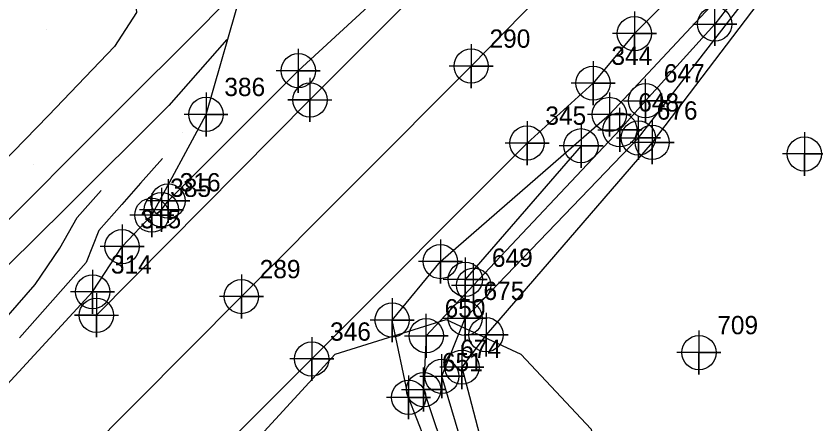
# Model space of a CAD drawing. Extents: x 1497074 to 1501343, y 481943 to 486114.
# Drawn here: x 1499153.8 to 1499263, y 485520.4 to 485576.1 of the extents above; entities that cross this region are included whole.
import ezdxf

# ---------------------------------------------------------------- set-up
doc = ezdxf.new("R2010")
doc.units = 0
for name, color, linetype in [('Exist DTM Breakline', 7, 'Continuous'), ('Exist DTM Breakline Cogo Point CELL', 7, 'Continuous'), ('Exist DTM Crownline', 7, 'Continuous'), ('Exist DTM Crownline Cogo Number', 7, 'Continuous'), ('Exist DTM Crownline Cogo Point CELL', 7, 'Continuous'), ('Exist DTM Regular Point CELL', 7, 'Continuous'), ('Exist DTM Regular Point Cogo Number', 7, 'Continuous'), ('Exist Hydro Stream or Body of Water', 7, 'Continuous'), ('Exist Hydro Stream or Body of Water Cogo Number', 7, 'Continuous'), ('Exist Hydro Stream or Body of Water Cogo Point CELL', 7, 'Continuous'), ('Exist Roads EOP', 7, 'Continuous'), ('Exist Roads EOP Cogo Number', 7, 'Continuous'), ('Exist Roads EOP Cogo Point CELL', 7, 'Continuous'), ('Exist Roads EOT', 7, 'Continuous'), ('Exist Roads EOT Cogo Point CELL', 7, 'Continuous'), ('PH Exist DTM Breakline', 7, 'Continuous'), ('PH Exist DTM Obscure Area', 7, 'Continuous'), ('PH Exist DTM Point', 7, 'Continuous')]:
    doc.layers.add(name, color=color, linetype=linetype)

msp = doc.modelspace()

# ---------------------------------------------------------------- linework, layer by layer
at = {"layer": 'Exist DTM Breakline'}
msp.add_line((1499230.94, 485558.36), (1499215.12, 485540.11), dxfattribs=at)
for points in [[(1499185.98, 485341), (1499182.42, 485376.38), (1499182.27, 485405.43), (1499187.88, 485425.83), (1499196.82, 485454.89), (1499202.61, 485465.75), (1499208.87, 485482.28), (1499210.41, 485491.89), (1499215.33, 485503.59), (1499207.38, 485524), (1499205.13, 485534.56), (1499211.72, 485542.55), (1499234.8, 485562.64), (1499257.12, 485586.54)], [(1499260.16, 485584.5), (1499240.65, 485558.83), (1499217.96, 485532.56), (1499214.66, 485528.12), (1499220.52, 485505.65), (1499216.85, 485483.92), (1499209.67, 485464.86), (1499198.25, 485439.29), (1499192.7, 485425), (1499191.35, 485405.79), (1499191.24, 485397.87), (1499188.24, 485373.03), (1499195.27, 485338.64)], [(1499173.62, 485549.63), (1499174.52, 485550.82), (1499192.31, 485568.61), (1499205.81, 485581.06)]]:
    msp.add_lwpolyline(points, dxfattribs=at)
at = {"layer": 'Exist DTM Breakline Cogo Point CELL'}
for points in [[(1499192.31, 485571.61), (1499192.31, 485565.61), (1499192.31, 485568.61), (1499195.31, 485568.61), (1499189.31, 485568.61)], [(1499234.8, 485565.64), (1499234.8, 485559.64), (1499234.8, 485562.64), (1499237.8, 485562.64), (1499231.8, 485562.64)], [(1499240.65, 485561.83), (1499240.65, 485555.83), (1499240.65, 485558.83), (1499243.65, 485558.83), (1499237.65, 485558.83)], [(1499230.94, 485561.36), (1499230.94, 485555.36), (1499230.94, 485558.36), (1499233.94, 485558.36), (1499227.94, 485558.36)], [(1499174.52, 485553.82), (1499174.52, 485547.82), (1499174.52, 485550.82), (1499177.52, 485550.82), (1499171.52, 485550.82)], [(1499211.72, 485545.55), (1499211.72, 485539.55), (1499211.72, 485542.55), (1499214.72, 485542.55), (1499208.72, 485542.55)], [(1499215.12, 485543.11), (1499215.12, 485537.11), (1499215.12, 485540.11), (1499218.12, 485540.11), (1499212.12, 485540.11)], [(1499205.13, 485537.56), (1499205.13, 485531.56), (1499205.13, 485534.56), (1499208.13, 485534.56), (1499202.13, 485534.56)], [(1499217.96, 485535.56), (1499217.96, 485529.56), (1499217.96, 485532.56), (1499220.96, 485532.56), (1499214.96, 485532.56)], [(1499214.66, 485531.12), (1499214.66, 485525.12), (1499214.66, 485528.12), (1499217.66, 485528.12), (1499211.66, 485528.12)], [(1499207.38, 485527), (1499207.38, 485521), (1499207.38, 485524), (1499210.38, 485524), (1499204.38, 485524)]]:
    msp.add_lwpolyline(points, dxfattribs=at)
for centre in [(1499192.31, 485568.61), (1499234.8, 485562.64), (1499230.94, 485558.36), (1499240.65, 485558.83), (1499174.52, 485550.82), (1499211.72, 485542.55), (1499215.12, 485540.11), (1499205.13, 485534.56), (1499217.96, 485532.56), (1499214.66, 485528.12), (1499207.38, 485524)]:
    msp.add_circle(centre, 2.34, dxfattribs=at)
at = {"layer": 'Exist DTM Crownline'}
msp.add_lwpolyline([(1498753.92, 485018.83), (1498767.97, 485036.35), (1498784.41, 485057.61), (1498813.33, 485094.71), (1498845.11, 485135.39), (1498876.05, 485175.22), (1498907.7, 485215.72), (1498939.87, 485257.15), (1498970.73, 485296.32), (1499001.6, 485335.5), (1499032.55, 485374.36), (1499053.88, 485400.5), (1499073.91, 485423.48), (1499090.49, 485441.64), (1499112.37, 485464.57), (1499148.43, 485501.47), (1499184.54, 485537.77), (1499215.93, 485569.25), (1499248.51, 485602.52), (1499285.02, 485638.96), (1499320.99, 485674.8), (1499344.91, 485698.57), (1499374.04, 485727.35), (1499398.21, 485750.96)], dxfattribs=at)
at = {"layer": 'Exist DTM Crownline Cogo Point CELL'}
for points in [[(1499215.93, 485572.25), (1499215.93, 485566.25), (1499215.93, 485569.25), (1499218.93, 485569.25), (1499212.93, 485569.25)], [(1499184.54, 485540.77), (1499184.54, 485534.77), (1499184.54, 485537.77), (1499187.54, 485537.77), (1499181.54, 485537.77)]]:
    msp.add_lwpolyline(points, dxfattribs=at)
for centre in [(1499215.93, 485569.25), (1499184.54, 485537.77)]:
    msp.add_circle(centre, 2.34, dxfattribs=at)
at = {"layer": 'Exist DTM Regular Point CELL'}
for points in [[(1499261.44, 485560.24), (1499261.44, 485554.24), (1499261.44, 485557.24), (1499264.44, 485557.24), (1499258.44, 485557.24)], [(1499247.04, 485533.12), (1499247.04, 485527.12), (1499247.04, 485530.12), (1499250.04, 485530.12), (1499244.04, 485530.12)]]:
    msp.add_lwpolyline(points, dxfattribs=at)
for centre in [(1499261.44, 485557.24), (1499247.04, 485530.12)]:
    msp.add_circle(centre, 2.34, dxfattribs=at)
at = {"layer": 'Exist Hydro Stream or Body of Water'}
for points in [[(1499257.73, 485586.04), (1499249.2, 485574.99), (1499239.74, 485564.51)], [(1499192.72, 485337.9), (1499186.72, 485373.56), (1499186.02, 485389.81), (1499189.55, 485398.75), (1499188.74, 485407.91), (1499191.43, 485426.99), (1499196.42, 485439.19), (1499206.35, 485461.87), (1499214.78, 485484.46), (1499216.03, 485490.1), (1499217.88, 485506.83), (1499211.92, 485526.88), (1499215.11, 485534.8), (1499238.77, 485559.43), (1499259.03, 485585.66)], [(1499239.74, 485564.51), (1499236.24, 485560.54), (1499216.26, 485539.33), (1499209.8, 485532.42), (1499209.43, 485525.06), (1499216.54, 485503.87), (1499211.37, 485491.89), (1499211.32, 485490.81), (1499211, 485482.57), (1499204.46, 485465.7), (1499198.37, 485454.49), (1499189.02, 485425.2), (1499187.48, 485405.82), (1499185.13, 485390.06), (1499184.69, 485374.49), (1499190.61, 485338.3)]]:
    msp.add_lwpolyline(points, dxfattribs=at)
at = {"layer": 'Exist Hydro Stream or Body of Water Cogo Point CELL'}
for points in [[(1499246.2, 485574.99), (1499252.2, 485574.99), (1499249.2, 485574.99), (1499249.2, 485571.99), (1499249.2, 485577.99)], [(1499236.74, 485564.51), (1499242.74, 485564.51), (1499239.74, 485564.51), (1499239.74, 485561.51), (1499239.74, 485567.51)], [(1499233.24, 485560.54), (1499239.24, 485560.54), (1499236.24, 485560.54), (1499236.24, 485557.54), (1499236.24, 485563.54)], [(1499235.77, 485559.43), (1499241.77, 485559.43), (1499238.77, 485559.43), (1499238.77, 485556.43), (1499238.77, 485562.43)], [(1499213.26, 485539.33), (1499219.26, 485539.33), (1499216.26, 485539.33), (1499216.26, 485536.33), (1499216.26, 485542.33)], [(1499212.11, 485534.8), (1499218.11, 485534.8), (1499215.11, 485534.8), (1499215.11, 485531.8), (1499215.11, 485537.8)], [(1499206.8, 485532.42), (1499212.8, 485532.42), (1499209.8, 485532.42), (1499209.8, 485529.42), (1499209.8, 485535.42)], [(1499208.92, 485526.88), (1499214.92, 485526.88), (1499211.92, 485526.88), (1499211.92, 485523.88), (1499211.92, 485529.88)], [(1499206.43, 485525.06), (1499212.43, 485525.06), (1499209.43, 485525.06), (1499209.43, 485522.06), (1499209.43, 485528.06)]]:
    msp.add_lwpolyline(points, dxfattribs=at)
for centre in [(1499249.2, 485574.99), (1499239.74, 485564.51), (1499236.24, 485560.54), (1499238.77, 485559.43), (1499216.26, 485539.33), (1499215.11, 485534.8), (1499209.8, 485532.42), (1499211.92, 485526.88), (1499209.43, 485525.06)]:
    msp.add_circle(centre, 2.34, dxfattribs=at)
at = {"layer": 'Exist Roads EOP'}
for points in [[(1499406.68, 485742.77), (1499382.28, 485717.88), (1499354.16, 485689.77), (1499330.28, 485665.86), (1499294.21, 485630.03), (1499257.75, 485593.24), (1499238.22, 485573.68), (1499232.58, 485566.91), (1499223.56, 485558.73), (1499194.15, 485529.24), (1499157.4, 485492.59), (1499121.26, 485455.44)], [(1499172.31, 485548.88), (1499179.71, 485562.65), (1499184.8, 485580.27), (1499188.78, 485607.06), (1499189.23, 485622.67), (1499188.38, 485633.27), (1499185.84, 485649.44), (1499182.84, 485660.02), (1499178.88, 485670.13), (1499176.46, 485674.89), (1499173.56, 485679.31), (1499157.76, 485701.6)], [(1498744.68, 485026.11), (1498757.92, 485043.98), (1498774.18, 485065.51), (1498803.2, 485102.83), (1498835.11, 485143.9), (1498866.39, 485184.06), (1498897.92, 485224.48), (1498930.45, 485265.81), (1498960.65, 485304.75), (1498991.78, 485343.69), (1499023.06, 485383.27), (1499044.83, 485409.1), (1499064.02, 485432.02), (1499081.8, 485451.06), (1499098.44, 485468.79), (1499108.29, 485478.99), (1499123.4, 485494.87), (1499138.72, 485510.78), (1499164.22, 485538.41), (1499168.24, 485544.59), (1499172.31, 485548.88)]]:
    msp.add_lwpolyline(points, dxfattribs=at)
at = {"layer": 'Exist Roads EOP Cogo Point CELL'}
for points in [[(1499238.22, 485576.68), (1499238.22, 485570.68), (1499238.22, 485573.68), (1499241.22, 485573.68), (1499235.22, 485573.68)], [(1499232.58, 485569.91), (1499232.58, 485563.91), (1499232.58, 485566.91), (1499235.58, 485566.91), (1499229.58, 485566.91)], [(1499179.71, 485565.65), (1499179.71, 485559.65), (1499179.71, 485562.65), (1499182.71, 485562.65), (1499176.71, 485562.65)], [(1499223.56, 485561.73), (1499223.56, 485555.73), (1499223.56, 485558.73), (1499226.56, 485558.73), (1499220.56, 485558.73)], [(1499173.62, 485552.63), (1499173.62, 485546.63), (1499173.62, 485549.63), (1499176.62, 485549.63), (1499170.62, 485549.63)], [(1499172.31, 485551.88), (1499172.31, 485545.88), (1499172.31, 485548.88), (1499175.31, 485548.88), (1499169.31, 485548.88)], [(1499168.24, 485547.59), (1499168.24, 485541.59), (1499168.24, 485544.59), (1499171.24, 485544.59), (1499165.24, 485544.59)], [(1499164.22, 485541.41), (1499164.22, 485535.41), (1499164.22, 485538.41), (1499167.22, 485538.41), (1499161.22, 485538.41)], [(1499194.15, 485532.24), (1499194.15, 485526.24), (1499194.15, 485529.24), (1499197.15, 485529.24), (1499191.15, 485529.24)]]:
    msp.add_lwpolyline(points, dxfattribs=at)
for centre in [(1499238.22, 485573.68), (1499232.58, 485566.91), (1499179.71, 485562.65), (1499223.56, 485558.73), (1499173.62, 485549.63), (1499172.31, 485548.88), (1499168.24, 485544.59), (1499164.22, 485538.41), (1499194.15, 485529.24)]:
    msp.add_circle(centre, 2.34, dxfattribs=at)
at = {"layer": 'Exist Roads EOT'}
msp.add_lwpolyline([(1499164.74, 485535.21), (1499193.9, 485564.62), (1499219.81, 485590.53), (1499263, 485633.71)], dxfattribs=at)
at = {"layer": 'Exist Roads EOT Cogo Point CELL'}
for points in [[(1499193.9, 485567.62), (1499193.9, 485561.62), (1499193.9, 485564.62), (1499190.9, 485564.62), (1499196.9, 485564.62)], [(1499164.74, 485538.21), (1499164.74, 485532.21), (1499164.74, 485535.21), (1499161.74, 485535.21), (1499167.74, 485535.21)]]:
    msp.add_lwpolyline(points, dxfattribs=at)
for centre in [(1499193.9, 485564.62), (1499164.74, 485535.21)]:
    msp.add_circle(centre, 2.34, dxfattribs=at)
at = {"layer": 'PH Exist DTM Breakline'}
for points in [[(1499153.17, 485673.71), (1499162.45, 485658.84), (1499165.18, 485653.77), (1499167.02, 485648.89), (1499168.88, 485643.09), (1499170.56, 485637.72), (1499171.57, 485631.53), (1499171.4, 485625.48), (1499170.63, 485618.57), (1499170.84, 485611.93), (1499171.01, 485605.52), (1499171.2, 485599.72), (1499170.74, 485593.96), (1499169.59, 485586.49), (1499169.76, 485581.42), (1499170.2, 485576.57), (1499167.23, 485571.91), (1499158.21, 485562.48), (1499132.52, 485536.14)], [(1499033.33, 485421.86), (1499038.75, 485428.05), (1499042.42, 485431.01), (1499046.18, 485433.54), (1499048.33, 485435.36), (1499050.55, 485437.83), (1499053.16, 485442.2), (1499056.29, 485447.97), (1499058.09, 485450.12), (1499066.63, 485459.29), (1499087.71, 485481.69), (1499111.87, 485506.97), (1499131.84, 485527.59), (1499149.97, 485545.53), (1499167.07, 485562.63), (1499179.36, 485574.9), (1499184.32, 485580.01)], [(1499182.56, 485572.89), (1499174.63, 485563.86), (1499160.52, 485549.79), (1499140.85, 485530.42), (1499113.26, 485502.35), (1499086.18, 485474.29), (1499062.04, 485447.92), (1499060.27, 485445.67), (1499058.22, 485441.12), (1499056.49, 485438.04), (1499054.74, 485435.42), (1499052.19, 485432.56), (1499050.32, 485430.5), (1499046.87, 485427.89), (1499042.32, 485424.66), (1499039.45, 485422.45), (1499036.52, 485418.7)], [(1499173.78, 485556.64), (1499170.74, 485553.24), (1499168.2, 485550.36), (1499165.05, 485546.8), (1499163.33, 485542.41), (1499154.23, 485532.15)], [(1499134.85, 485515.78), (1499151.43, 485533.79), (1499156.37, 485539.4), (1499159.74, 485544.39), (1499162.09, 485548.56), (1499165.38, 485552.24)]]:
    msp.add_lwpolyline(points, dxfattribs=at)
at = {"layer": 'PH Exist DTM Obscure Area'}
msp.add_lwpolyline([(1499149.23, 485468.18), (1499156.41, 485483.23), (1499168.58, 485498.07), (1499183.61, 485514.9), (1499197.34, 485529.91), (1499212.52, 485534.63), (1499222.72, 485529.9), (1499232.31, 485519.64), (1499234.08, 485508.3), (1499229.88, 485495.42), (1499220.2, 485480.12), (1499219.41, 485460.49), (1499225.77, 485441.12), (1499228.02, 485432.48), (1499228.46, 485418.31), (1499232.97, 485402.23), (1499241.35, 485391.01), (1499261.85, 485386.79), (1499278, 485376.9), (1499289.37, 485366.83), (1499301.98, 485354.41), (1499307.09, 485337.87), (1499311.37, 485319.99), (1499317.64, 485301.29)], dxfattribs=at)
at = {"layer": 'PH Exist DTM Point'}
for p, q in [((1499157.95, 485574.21), (1499157.95, 485574.21)), ((1499176.47, 485560.14), (1499176.47, 485560.14)), ((1499156.2, 485555.77), (1499156.2, 485555.77))]:
    msp.add_line(p, q, dxfattribs=at)

# ---------------------------------------------------------------- texts
at = {"layer": 'Exist DTM Crownline Cogo Number'}
for s, p in [('290', (1499218.43, 485571.75)), ('289', (1499187.04, 485540.27))]:
    msp.add_text(s, height=2.5, dxfattribs=at).set_placement(p)
at = {"layer": 'Exist DTM Regular Point Cogo Number'}
msp.add_text('709', height=2.5, dxfattribs=at).set_placement((1499249.54, 485532.62))
at = {"layer": 'Exist Hydro Stream or Body of Water Cogo Number'}
for s, p in [('647', (1499242.24, 485567.01)), ('648', (1499238.74, 485563.04)), ('676', (1499241.27, 485561.93)), ('649', (1499218.76, 485541.83)), ('675', (1499217.61, 485537.3)), ('650', (1499212.3, 485534.92)), ('674', (1499214.42, 485529.38)), ('651', (1499211.93, 485527.56))]:
    msp.add_text(s, height=2.5, dxfattribs=at).set_placement(p)
at = {"layer": 'Exist Roads EOP Cogo Number'}
for s, p in [('344', (1499235.08, 485569.41)), ('386', (1499182.21, 485565.15)), ('345', (1499226.06, 485561.23)), ('316', (1499176.12, 485552.13)), ('385', (1499174.81, 485551.38)), ('315', (1499170.74, 485547.09)), ('314', (1499166.72, 485540.91)), ('346', (1499196.65, 485531.74))]:
    msp.add_text(s, height=2.5, dxfattribs=at).set_placement(p)

doc.saveas('drawing.dxf')
